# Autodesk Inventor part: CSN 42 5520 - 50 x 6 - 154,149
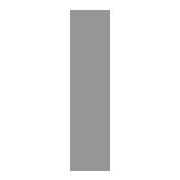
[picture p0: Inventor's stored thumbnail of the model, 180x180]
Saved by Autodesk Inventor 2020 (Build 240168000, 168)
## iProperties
Created: 2019-01
Part Number: CSN 42 5520 - 50 x 6 - 154,149
Material: Ocel
Description: Tyč
Document SubType Name: Modeling
Standard: CSN 42 5520
Designer: doma
Standards Organization: CSN
Language: cs-CZ
Size Designation: 50 x 6 - 154,149
Categories: <MemberInstance><Categories><Category DisplayName="Konstrukční profily" InternalName="089c4875-fa83-4c05-b084-43b9cc11f5ed" Mnemonic="GRDR"><CategoryParameter D
Stock Number: 50 x 6
Density: 7.85 g/cm^3
Appearance: Plech
Mass: 363.021 g
Surface Area: 178.647 cm^2
Volume: 46.2447 cm^3
IsCustomPart: 1
G_L: 154,149 mm
Author: doma
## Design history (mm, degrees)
node "Počáteční rovina"
node "Koncová rovina"
sketch "Náčrt"
  geometry: L1 (3, -25)-(-3, -25); L2 (-3, -25)-(-3, 25); L3 (-3, 25)-(3, 25); L4 (3, 25)-(3, -25); L5 (-6, 0)-(8, 0); L6 (0, -30)-(0, 40); L7 (0, 54)-(0, -44) reference; L8 (-9.2, 0)-(13.2, 0) reference
  constraints: 12 end point, 2 collinear, 2 parallel, 1 horizontal, 1 perpendicular
  dimensions: "d0" = 50 distance between parallel lines of L3 L1 (= G_W); "d1" = 6 distance between parallel lines of L4 L2 (= G_H); "d4" = 3 distance between parallel lines of L6 L4 (= 0.5 x d1); "d5" = 25 distance between parallel lines of L5 L3 (= 0.5 x d0)
extrude "Těleso" new body sketch "Náčrt" stored distance "d2" = 154.149 (= G_L); taper "d3" = 0 deg
node "Driven Length"
  sketch "Sketch3"
    geometry: L1 (0, 0)-(10, 0) reference
    constraints: 2 end point, 1 horizontal
  workplane "Work Plane3"
  sketch "Sketch4"
    geometry: L1 (-2, 0)-(12, 0) reference; L2 (-2, 154.149)-(12, 154.149) reference
    dimensions: "d9" = 154.149 distance between parallel lines of L1 L2 (derived)
body "Solid1"
other parameters: "G_W" = 50 [user parameter; used in 1 equation term], "G_H" = 6 [user parameter; used in 1 equation term], "G_L" = 154.149 (= d9) [user parameter; used in 1 equation term], "G_OFFSET_START" = 0 [user parameter; used in 1 equation term], "G_OFFSET_END" = 0 [user parameter; used in 1 equation term], "d6" = 0 (computed from G_OFFSET_START), "d7" = 154.149 (= G_OFFSET_END + B_L), "B_L" = 154.149 [user parameter; used in 1 equation term], "d8" = 90 deg
